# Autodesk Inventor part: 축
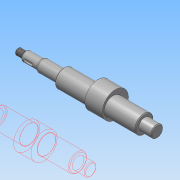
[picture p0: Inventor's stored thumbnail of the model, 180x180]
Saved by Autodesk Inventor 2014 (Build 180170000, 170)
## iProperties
Created: 2015-12
Part Number: 축
Document SubType Name: Modeling
Designer: mdu
Density: 7.86 g/cm^3
Material: 강철, 연강
Mass: 489.709 g
Surface Area: 127.382 cm^2
Volume: 62.304 cm^3
Appearance: 강철
Author: mdu
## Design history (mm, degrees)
sketch "스케치1"
  geometry: L1 (62, 100.9)-(62, 67.1) reference; L2 (51, 101.2)-(51, 84) reference; L3 (-51, 84)-(-51, 101.2) reference; L4 (-62, 67.1)-(-62, 100.9) reference; L5 (-51.6, 91.5)-(-61.4, 91.5) reference; L6 (51.6, 91.5)-(61.4, 91.5) reference; L7 (67, 84)-(-109, 84); L8 (-77, 64.201)-(-77, 103.799) reference; L9 (67, 84)-(67, 91.5); L10 (67, 91.5)-(51, 91.5); L11 (51, 91.5)-(51, 95.5); L12 (51, 95.5)-(-51, 95.5); L13 (-51, 95.5)-(-51, 91.5); L14 (-51, 91.5)-(-79, 91.5); L15 (-79, 91.5)-(-79, 90); L16 (-79, 90)-(-99, 90); L17 (-99, 90)-(-99, 87); L18 (-100.5, 88)-(-109, 88); L19 (-109, 88)-(-109, 84); L20 (-99, 87)-(-100.5, 87); L21 (-100.5, 87)-(-100.5, 88); 2 further points
  constraints: 32 end point, 7 parallel, 6 point on line, 5 perpendicular, 2 collinear, 2 horizontal, 1 midpoint, 4 other
  dimensions: "d0" = 5 distance from line of L7.start L1; "d2" = 2 distance between parallel lines of L15 L8; "d3" = 23 diameter of L12 L7; "d4" = 12 diameter of L16 L7; "d5" = 1.5 distance of L17.end L20.end; "d6" = 6 diameter of L20 L7; "d7" = 20 distance of L15.end L16.end; "d8" = 10 distance between parallel lines of L17 L19; "d9" = 8 diameter of L18 L7
revolve "회전1" sketch "스케치1" stored, may be unused: angle "d10" = 90 deg
sketch "스케치2"
  geometry: C1 r 11.5 at (84, 0) reference; C2 r 11.5 at (84, 0) reference; C3 r 16.5 at (87, 0); 1 further point
  constraints: 1 centre point, 1 horizontal alignment
  dimensions: "d11" = 33 diameter of C3; "d12" = 3 distance of C3.centre C1.centre
extrude "돌출1" join sketch "스케치2" stored distance "d13" = 22; taper "d14" = 0 deg
chamfer "모따기1" distance "d15" = 1; stored, may be unused: second distance "d16" = 2, angle "d17" = 45 deg
feature "스레드1" dims "d18" = 10, "d19" = 0
node "작업 평면1"
sketch "스케치3"
  geometry: L1 (-5, -2)-(3, -2); L2 (3, 2)-(-5, 2); L3 (-10, -5)-(-10, 5) reference; A1 r 2 centre (3, 0) between (3, -2) and (3, 2); A2 r 2 centre (-5, 0) between (-5, 2) and (-5, -2); 2 further points
  constraints: 4 end point, 4 point on circle, 4 tangent, 2 centre point, 1 horizontal, 1 horizontal alignment, 1 midpoint, 1 parallel
  dimensions: "d20" = 4 distance between parallel lines of L1 L2; "d21" = 12 dimension on A1 A2; "d22" = 3 distance edge to line of A2 L3
extrude "돌출2" cut sketch "스케치3" distance "d23" = 2.5; taper "d24" = 0 deg
fillet "모깎기1" dims "d25" = 0.3
fillet "모깎기2" dims "d26" = 3
node "솔리드1"
node "참조1"
node "참조2"
node "참조3"
node "참조4"
node "참조5"
node "투영된 루프1"
